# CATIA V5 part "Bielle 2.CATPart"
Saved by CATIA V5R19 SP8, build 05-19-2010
Part number: Bielle 2
Publications: "Arête", "Arête1", "Arête2"
Bounding box of the stored display mesh (mm): x -5 to 5, y 61.424 to 184.537, z 79.925 to 152.729
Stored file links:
  C:\Users\thinkmotion1\Desktop\Khaled_IAO_Pack2\IAO_2010_1412_jclement\Non_Optimise\Bielle 2.CATPart
  C:\Users\thinkmotion1\Desktop\Khaled_IAO_Pack2\IAO_2010_1412_jclement\Non_Optimise\Synthese IAO_2.CATProduct
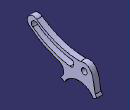
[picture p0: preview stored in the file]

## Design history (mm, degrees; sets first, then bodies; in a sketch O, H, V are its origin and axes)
Set1
  DatumCurve1: linked copy from another document
  DatumCurve2: linked copy from another document
  Sketch1 on yz-plane, origin (0, 0, 0), H (0, 1, 0), V (0, 0, 1)
    arc A1 centre (155.7499, 248.4263) radius 134.991 from (74.6129, 140.5403) to (137.5578, 114.6667) ccw
    point P2 (74.6129, 140.5403)
    point P3 (137.5578, 114.6667)
    reference projected arc E1 centre (74.6129, 140.5403) radius 6 from (78.2841, 145.2861) to (70.9417, 135.7946) ccw from edge [face of Pad1 from Sketch2.A3 | start face of Pad1]
    reference projected arc E2 centre (137.5578, 114.6667) radius 5.9994 from (136.7493, 108.722) to (138.3663, 120.6114) ccw from edge [face of Pad1 from Sketch2.A6 | start face of Pad1]
    radius A1 = 134.991
    concentricity: P2 E1, P3 E2
Body1 (main body)
  Sketch2 on yz-plane, origin (0, 0, 0), H (0, 1, 0), V (0, 0, 1)
    spline S1 through (155.2242, 125.1705) (129.7076, 127.8657) (77.8783, 150.5835)
    spline S2 through (124.8788, 89.7886) (125.1556, 97.7562) (121.2871, 104.0425) (115.968, 106.9438) (103.8789, 112.0212) (97.3509, 114.6808) (74.1399, 127.7369) (65.3475, 134.4972)
    spline S3 through (155.2242, 125.1705) (169.9218, 123.4313) (177.9934, 108.1171) (179.2023, 101.589) (181.5345, 88.0692)
    arc A1 centre (71.6129, 142.5403) radius 10.1955 from (77.8783, 150.5835) to (65.3475, 134.4972) ccw
    point P1 (77.8783, 150.5835)
    point P2 (65.3475, 134.4972)
    point P3 (71.6129, 142.5403)
    arc A2 centre (152.4617, 64.3832) radius 37.5 from (181.5345, 88.0692) to (124.8788, 89.7886) ccw
    point P5 (124.8788, 89.7886)
    point P6 (181.5345, 88.0692)
    construction line L1 (135.1456, 96.9311) -> (142.5575, 151.4275)
    construction line L2 (62.7046, 125.1465) -> (78.2841, 145.2861)
    arc A3 centre (74.6129, 140.5403) radius 6 from (78.2841, 145.2861) to (70.9417, 135.7946) ccw
    point P11 (74.6129, 140.5403)
    arc A4 centre (155.7499, 248.4263) radius 128.9916 from (138.3663, 120.6114) to (78.2841, 145.2861) cw
    point P13 (138.3663, 120.6114)
    arc A5 centre (155.7499, 248.4263) radius 140.9905 from (136.7493, 108.722) to (70.9417, 135.7946) cw
    point P15 (136.7493, 108.722)
    point P16 (70.9417, 135.7946)
    point P17 (70.9417, 135.7946)
    arc A6 centre (137.5578, 114.6667) radius 5.9994 from (138.3663, 120.6114) to (136.7493, 108.722) cw
    point P19 (155.2242, 125.1705)
    point P20 (155.2242, 125.1705)
    point P21 (77.8783, 150.5835)
    point P22 (65.3475, 134.4972)
    point P23 (181.5345, 88.0692)
    point P24 (124.8788, 89.7886)
    radius A2 = 37.5
    radius A3 = 6
    distance P11 P3 H = 3
    distance P3 P11 V = 2
    coincidence: P19 P20, P21 P1, P22 P2, A2 P23, P24 A2, P24 P5, P23 P6, P11 L2, P13 L1, P15 L1, P16 A3, P16 L2, L2 P17
    concentricity: A5 A4
    tangency: A6 A4, A6 A5
  Pad1: profile Sketch2, direction (1, 0, 0), length 5, mirrored extent
  Sketch3 on yz-plane, origin (0, 0, 0), H (0, 1, 0), V (0, 0, 1)
    arc A1 centre (152.4617, 64.3832) radius 37.5 from (184.5375, 83.8099) to (120.386, 83.8099) ccw
    point P1 (152.4617, 64.3832)
    reference projected arc E1 centre (152.4617, 64.3832) radius 37.5 from (181.5345, 88.0692) to (124.8788, 89.7886) ccw from edge [face of Pad1 from Sketch2.A2 | end face of Pad1]
    arc A2 centre (152.4617, 64.3832) radius 30 from (178.1223, 79.9246) to (126.8011, 79.9246) ccw
    line L1 (120.386, 83.8099) -> (126.8011, 79.9246)
    line L2 (178.1223, 79.9246) -> (184.5375, 83.8099)
    radius A2 = 30
    coincidence: A1 E1, L1 P1
  Pad2: profile Sketch3, direction (1, 0, 0), length 5, mirrored extent
  Sketch4 on face of Pad2, origin (5, 0, 0), H (0, 1, 0), V (0, 0, 1)
    circle A1 centre (161.9769, 113.7106) radius 5
    reference projected circle E1 centre (161.9769, 113.7106) radius 5 from edge of DatumCurve1
    coincidence: A1 E1
  Pocket1: profile Sketch4, direction (-1, 0, 0), through (limit type 6)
